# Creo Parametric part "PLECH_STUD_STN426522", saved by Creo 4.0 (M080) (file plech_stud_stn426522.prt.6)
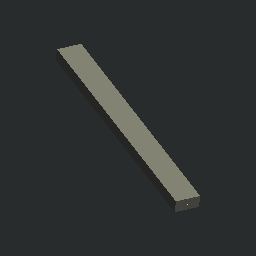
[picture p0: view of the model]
Units: Custom; MM, KILOGRAM, SECS
Materials in the file: OCEL_N

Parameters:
  NORMINFO = "Stabstahl Formstahl; Kaltgewalzter rundkantiger U-Stahl"
  FESTIGKEIT = "."
  N_D = "0"
  B_D = "5"
  KATEGORIE = "0"
  DESIGNER = "."
  DATE = "."
  FORMAT = "."
  MOD_INDEX_1 = "."
  MOD_INDEX_2 = "."
  MOD_INDEX_3 = "."
  MOD_INDEX_4 = "."
  MOD_INDEX_5 = "."
  MOD_INDEX_6 = "."
  MOD_INDEX_7 = "."
  MOD_INDEX_8 = "."
  MOD_NOTE_1 = "."
  MOD_NOTE_2 = "."
  MOD_NOTE_3 = "."
  MOD_NOTE_4 = "."
  MOD_NOTE_5 = "."
  MOD_NOTE_6 = "."
  MOD_NOTE_7 = "."
  MOD_NOTE_8 = "."
  MOD_DATE_1 = "."
  MOD_DATE_2 = "."
  MOD_DATE_3 = "."
  MOD_DATE_4 = "."
  MOD_DATE_5 = "."
  MOD_DATE_6 = "."
  MOD_DATE_7 = "."
  MOD_DATE_8 = "."
  MOD_NAME_1 = "."
  MOD_NAME_2 = "."
  MOD_NAME_3 = "."
  MOD_NAME_4 = "."
  MOD_NAME_5 = "."
  MOD_NAME_6 = "."
  MOD_NAME_7 = "."
  MOD_NAME_8 = "."
  NAZOV = "PLECH_STUD_STN426522"
  ROZMER = "PL 10x5x100"
  NORMA = "STN 42 6522"
  HMOTNOST_HR = "."
  MATERIAL_ZAKL = "."
  PTC_MATERIAL_NAME = "OCEL_N"

Other parameters: L, T, QUERSCHNITT, B, HMOTNOST, HUSTOTA, HMOTNOST_1, D23, D1

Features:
  1. datum plane "Y-Y"
  2. datum plane "X-X"
  3. datum plane "Z-Z"
  4. coordinate system
  5. datum axis
  6. datum axis
  7. datum axis
  8. protrusion
  9. datum point "PNT0"
  10. datum point "PNT1"
  11. curve

Other named items: ZZ, XX, YY, CS0

Named dimensions: dicke, Laenge, laenge_nf, breite

Layers: BEZUG, BEZUGSACHSEN, KONSTRUKTIONSELEMENTE, PLAZIERUNG, PROFIL_NEUTRALE_FASER

Notes: Flachstahl | FL 10x5x100 DIN 1017 | Gewicht:  | 0.087 | Querschnittsfläche: A=  | 0.500 |  cm²

Family table entries: GENERIC, PLECH_5X2, PLECH_STUD_STN426522, value(d_val), value(i_val), PLECH_5X3, PLECH_STUD_STN426522, PLECH_10X2, PLECH_STUD_STN426522, !/$, PLECH_10X3, PLECH_STUD_STN426522, !/$, PLECH_10X4, PLECH_STUD_STN426522, !/$, PLECH_10X5, PLECH_STUD_STN426522, !/$, PLECH_10X6, PLECH_STUD_STN426522, !/$, PLECH_10X8, PLECH_STUD_STN426522, !/$, 2/ , PLECH_14X2, PLECH_STUD_STN426522, !/,, PLECH_14X3, PLECH_STUD_STN426522, !/,, PLECH_14X4, PLECH_STUD_STN426522, !/,, PLECH_14X5, PLECH_STUD_STN426522, !/,, PLECH_14X6, PLECH_STUD_STN426522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

Surfaces: 6 plane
